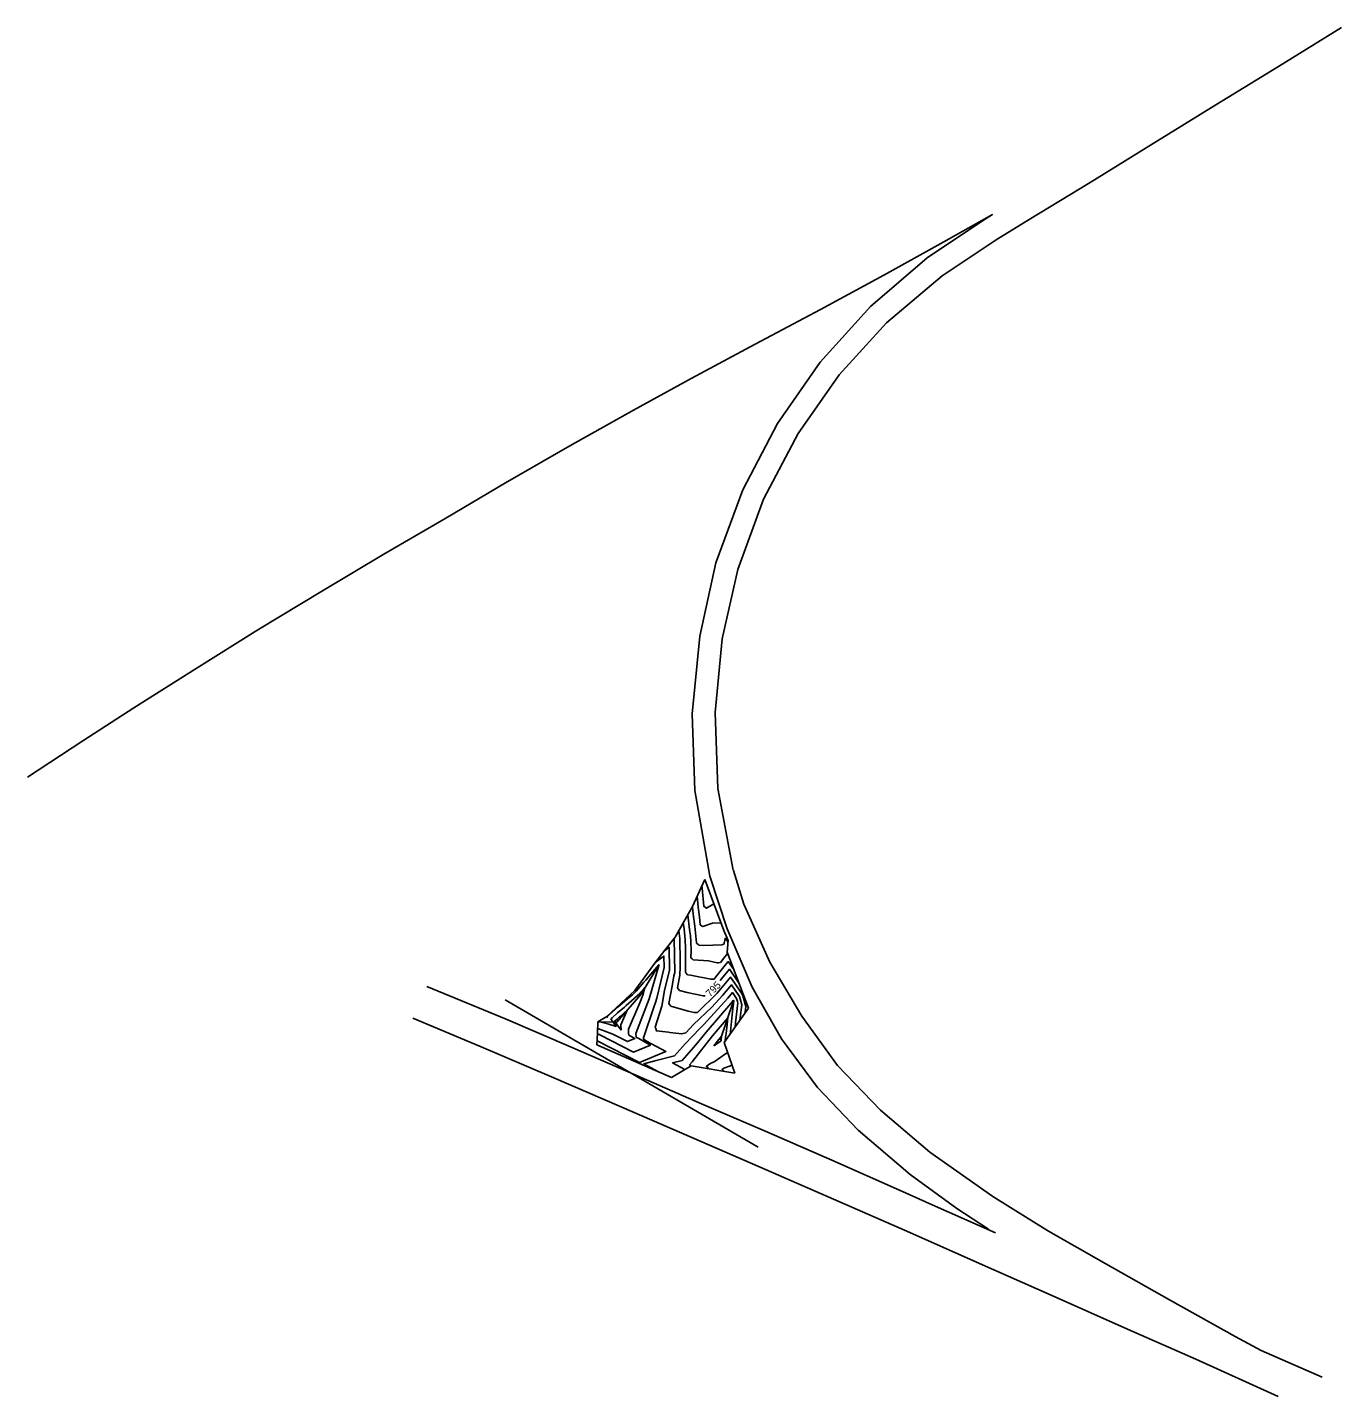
# Model space of a CAD drawing. Extents: x -5011 to 2414078, y -634 to 600034.
# Drawn here: x 2413180 to 2414078, y 599099 to 600034 of the extents above; entities that cross this region are included whole.
import ezdxf

# ---------------------------------------------------------------- set-up
doc = ezdxf.new("R2010")
doc.units = 0
for name, color, linetype in [('Default', 7, 'Continuous'), ('DESIGN - CONTOURS - Index with Text', 7, 'Continuous'), ('DESIGN - CONTOURS - Intermediate with optional Text', 7, 'Continuous'), ('DESIGN - DRAINAGE - Special Ditches', 7, 'Continuous'), ('DESIGN - ROW - Slope Lines', 7, 'Continuous'), ('SURVEY - TRANSPORTATION - Roads', 7, 'Continuous')]:
    doc.layers.add(name, color=color, linetype=linetype)

msp = doc.modelspace()

# ---------------------------------------------------------------- linework, layer by layer
at = {"layer": 'Default'}
msp.add_line((2413506.9, 599369.76), (2413679.75, 599269.14), dxfattribs=at)
at = {"layer": 'DESIGN - CONTOURS - Index with Text'}
for points in [[(2413641.24, 599447.27), (2413641.32, 599447.25), (2413641.38, 599446.55), (2413641.39, 599446.43), (2413641.39, 599446.43), (2413641.39, 599446.42), (2413641.39, 599446.42), (2413641.4, 599446.29), (2413641.4, 599446.28), (2413641.41, 599446.25), (2413641.44, 599445.95), (2413641.44, 599445.9), (2413642.57, 599433.63), (2413644.41, 599432.42), (2413644.41, 599432.42), (2413644.41, 599432.42), (2413644.42, 599432.42), (2413644.42, 599432.42), (2413644.42, 599432.42), (2413644.42, 599432.42), (2413649.52, 599435.25)], [(2413643.58, 599372.42), (2413642.68, 599372.4), (2413642.19, 599372.43), (2413631.18, 599374.64), (2413625.99, 599376.16), (2413625.13, 599377.27), (2413624.69, 599377.93), (2413626.32, 599386.57), (2413626.42, 599392.29), (2413626.37, 599395.71), (2413626.12, 599411.69), (2413625.49, 599417.09)], [(2413666.78, 599380.8), (2413660.04, 599390.56), (2413654.66, 599383.96), (2413653.83, 599382.95)], [(2413579.07, 599356.67), (2413579.96, 599357.44), (2413583.73, 599360.73), (2413588.34, 599364.74), (2413589.55, 599365.8), (2413598.98, 599374.01), (2413599.89, 599375.08), (2413600.09, 599375.31), (2413600.4, 599375.68), (2413600.72, 599376.04), (2413600.86, 599376.21), (2413602.39, 599378.02), (2413600.91, 599372.89), (2413598.94, 599367.7), (2413591.05, 599349.7), (2413591.21, 599346.72), (2413591.27, 599345.64), (2413591.57, 599345.44), (2413591.83, 599345.29), (2413595.51, 599343.27), (2413590.45, 599341.19), (2413580.48, 599346.29), (2413570.07, 599350.09)], [(2413570.54, 599354.85), (2413577.81, 599352.99), (2413582.7, 599351.57), (2413579.07, 599356.67)], [(2413633.62, 599324.5), (2413632.91, 599325.33), (2413634.72, 599327.34), (2413648.48, 599345.19), (2413658.96, 599357.41), (2413658.47, 599352.96), (2413657.77, 599346.62), (2413657.61, 599345.42), (2413657.48, 599344.4), (2413657.11, 599341.46)]]:
    msp.add_lwpolyline(points, dxfattribs=at)
at = {"layer": 'DESIGN - CONTOURS - Intermediate with optional Text'}
for points in [[(2413654.36, 599422.22), (2413648.5, 599422.08), (2413641.88, 599419.7), (2413640.96, 599420.19), (2413640.1, 599420.96), (2413639.55, 599426.45), (2413638.7, 599432.97), (2413638.25, 599437.92), (2413638.24, 599437.94), (2413638.23, 599438.05), (2413638.23, 599438.06), (2413638.23, 599438.07), (2413638.23, 599438.11), (2413638.23, 599438.11), (2413638.23, 599438.12), (2413638.23, 599438.12), (2413638.22, 599438.16), (2413638.03, 599440.22), (2413637.99, 599440.23)], [(2413659.34, 599400.13), (2413658.64, 599401.15), (2413658.08, 599400.46), (2413657.03, 599399.17), (2413653.92, 599395.25), (2413652.36, 599395.01), (2413651.69, 599395), (2413645.7, 599396.25), (2413635.38, 599396.97), (2413634.71, 599397.73), (2413633.82, 599398.48), (2413633.9, 599403.07), (2413633.8, 599409.48), (2413633.41, 599413.4), (2413633.04, 599416.24), (2413632.83, 599417.81), (2413631.67, 599427.85)], [(2413659.2, 599409.07), (2413657.1, 599411.73), (2413656.61, 599409.04), (2413656.61, 599409.04), (2413656.6, 599409.01), (2413656.41, 599407.99), (2413656.37, 599407.76), (2413654.8, 599407.22), (2413642.68, 599406.92), (2413639.26, 599407.16), (2413639.22, 599407.21), (2413637.93, 599408.29), (2413637.63, 599408.57), (2413636.48, 599419.93), (2413635.4, 599428.27), (2413634.8, 599432.91), (2413634.76, 599433.24)], [(2413663.06, 599390.47), (2413659.34, 599395.85), (2413656.37, 599392.21), (2413650.77, 599385.34), (2413649.57, 599383.84), (2413648.97, 599383.74), (2413647.39, 599383.72), (2413633.39, 599386.65), (2413631.5, 599386.78), (2413630.2, 599388.25), (2413629.99, 599388.42), (2413630.16, 599397.68), (2413630.04, 599405.36), (2413629.96, 599410.59), (2413629.08, 599418.16), (2413628.58, 599422.47)], [(2413670.69, 599360.51), (2413670.79, 599361.32), (2413671.2, 599365.05), (2413669.19, 599372.36), (2413668.87, 599373.51), (2413663.47, 599381.32), (2413660.74, 599385.27), (2413652.95, 599375.71), (2413651.82, 599374.34), (2413638.17, 599361.06), (2413637.45, 599361.05), (2413635.92, 599361.12), (2413631.89, 599361.93), (2413620, 599365.41), (2413619.83, 599365.63), (2413618.74, 599367.25), (2413620.96, 599379), (2413622.15, 599386), (2413622.71, 599388.3), (2413622.33, 599411.6), (2413621.85, 599411.24)], [(2413598.54, 599326.86), (2413616.66, 599334.31), (2413603.5, 599341.56), (2413602.55, 599342.08), (2413601.47, 599342.81), (2413601.42, 599343.66), (2413608.39, 599364.79), (2413609.55, 599367.85), (2413610.4, 599370.79), (2413615.5, 599391.76), (2413615.37, 599399.63), (2413613.79, 599398.44), (2413609.13, 599394.9)], [(2413667.29, 599355.75), (2413667.53, 599357.65), (2413668.5, 599366.34), (2413667.36, 599370.47), (2413666.92, 599372.05), (2413661.45, 599379.98), (2413655.43, 599372.61), (2413648.18, 599364.64), (2413635.52, 599352.74), (2413630.21, 599347.05), (2413629.36, 599346.88), (2413627.6, 599346.53), (2413619.45, 599347.45), (2413618.54, 599347.55), (2413610.22, 599348.48), (2413609.71, 599350.04), (2413609.38, 599351.01), (2413613.88, 599365.34), (2413615.69, 599376), (2413619.1, 599390.03), (2413618.85, 599405.62), (2413615.73, 599403.26), (2413615.49, 599403.07)], [(2413576.48, 599358.18), (2413577.94, 599359.45), (2413584.17, 599364.88), (2413591.76, 599371.5), (2413593.76, 599373.23), (2413596.38, 599375.52), (2413600.55, 599380.38), (2413601.48, 599381.47), (2413602.9, 599383.13), (2413604.35, 599384.81), (2413604.98, 599385.56), (2413611.76, 599393.55), (2413611.85, 599393.62), (2413611.89, 599393.64), (2413611.89, 599393.48), (2413611.79, 599393.06), (2413605.23, 599370.37), (2413596.25, 599346.72), (2413596.24, 599346.68), (2413596.37, 599344.23), (2413597.06, 599343.76), (2413597.66, 599343.43), (2413606.08, 599338.79), (2413594.49, 599334.02), (2413571.66, 599345.72), (2413569.88, 599346.37)], [(2413663.9, 599350.99), (2413664.28, 599353.97), (2413665.79, 599367.64), (2413665.53, 599368.59), (2413664.98, 599370.59), (2413662.15, 599374.69), (2413659.04, 599370.88), (2413642.59, 599352.81), (2413639.84, 599350.23), (2413629.88, 599339.54), (2413622.54, 599331.37), (2413610.01, 599328.14), (2413601.69, 599326), (2413611.53, 599320.56)], [(2413660.5, 599346.23), (2413660.51, 599346.26), (2413660.74, 599348.12), (2413661.02, 599350.29), (2413662.3, 599361.82), (2413663.09, 599368.94), (2413663.03, 599369.13), (2413662.85, 599369.4), (2413662.64, 599369.15), (2413660.97, 599367.3), (2413644.16, 599347.71), (2413638.39, 599340.22), (2413634.27, 599335.63), (2413627.73, 599328.35), (2413621.27, 599326.68), (2413629.59, 599322.08)], [(2413586.06, 599348.98), (2413585.87, 599352.72), (2413590.19, 599362.59), (2413585.34, 599358.36), (2413584.91, 599357.99), (2413583.3, 599356.59), (2413581.98, 599355.43), (2413581.66, 599355.16), (2413586.06, 599348.98)], [(2413575.88, 599358.06), (2413576.74, 599357.81), (2413576.48, 599358.18)], [(2413569.66, 599341.65), (2413598.54, 599326.86)], [(2413649.41, 599338.28), (2413652.8, 599342.68), (2413654.73, 599344.92), (2413654.64, 599344.11), (2413654.51, 599342.94), (2413654.48, 599342.72), (2413654.46, 599342.53), (2413654.36, 599341.77), (2413653.66, 599341.28), (2413652.74, 599340.63), (2413651.02, 599339.41), (2413650.82, 599339.27), (2413649.84, 599338.58), (2413649.67, 599338.46), (2413649.41, 599338.28)], [(2413646.12, 599322.67), (2413644.38, 599324.31), (2413647.38, 599326.41), (2413649.15, 599327.02), (2413649.69, 599327.4), (2413654.26, 599330.59), (2413656.69, 599332.29), (2413658.57, 599333.6), (2413659.02, 599333.29)], [(2413656.27, 599320.96), (2413655.05, 599322.11), (2413656.25, 599322.95), (2413660.23, 599324.34), (2413660.28, 599324.38), (2413660.74, 599324.7), (2413660.98, 599324.87), (2413661.17, 599325), (2413661.78, 599324.59), (2413662.1, 599324.58)]]:
    msp.add_lwpolyline(points, dxfattribs=at)
at = {"layer": 'DESIGN - DRAINAGE - Special Ditches'}
for points in [[(2413611.81, 599393.52), (2413599.7, 599373.59), (2413583.06, 599354.35), (2413570.29, 599354.7)], [(2413662.9, 599369.03), (2413653.78, 599342.11)]]:
    msp.add_lwpolyline(points, dxfattribs=at)
at = {"layer": 'DESIGN - ROW - Slope Lines'}
for p, q in [((2413643.35, 599451.87), (2413634.86, 599433.41)), ((2413656.3, 599417.01), (2413643.35, 599451.87)), ((2413622.92, 599412.61), (2413634.86, 599433.41)), ((2413634.86, 599433.41), (2413622.92, 599412.61)), ((2413659.33, 599410.32), (2413656.3, 599417.01)), ((2413616, 599403.72), (2413622.92, 599412.61)), ((2413622.92, 599412.61), (2413616, 599403.72)), ((2413658.48, 599402.37), (2413659.33, 599410.32)), ((2413658.48, 599402.37), (2413659.33, 599410.32)), ((2413609.08, 599394.83), (2413616, 599403.72)), ((2413616, 599403.72), (2413609.08, 599394.83)), ((2413665.85, 599383.22), (2413658.48, 599402.37)), ((2413665.85, 599383.22), (2413658.48, 599402.37)), ((2413595.38, 599376.1), (2413609.08, 599394.83)), ((2413609.08, 599394.83), (2413595.38, 599376.1)), ((2413673.23, 599364.08), (2413665.85, 599383.22)), ((2413673.23, 599364.08), (2413665.85, 599383.22)), ((2413576.28, 599358.3), (2413595.38, 599376.1)), ((2413595.38, 599376.1), (2413576.28, 599358.3)), ((2413656.46, 599340.55), (2413673.23, 599364.08)), ((2413656.46, 599340.55), (2413673.23, 599364.08)), ((2413570.29, 599354.7), (2413569.91, 599346.82)), ((2413570.29, 599354.7), (2413569.91, 599346.82)), ((2413576.28, 599358.3), (2413570.29, 599354.7)), ((2413576.28, 599358.3), (2413570.29, 599354.7)), ((2413569.91, 599346.82), (2413569.53, 599338.94)), ((2413569.91, 599346.82), (2413569.53, 599338.94)), ((2413569.53, 599338.94), (2413620.53, 599316.62)), ((2413569.53, 599338.94), (2413620.53, 599316.62)), ((2413663.83, 599319.69), (2413656.46, 599340.55)), ((2413663.83, 599319.69), (2413656.46, 599340.55)), ((2413620.53, 599316.62), (2413633.97, 599324.72)), ((2413620.53, 599316.62), (2413633.97, 599324.72)), ((2413633.97, 599324.72), (2413663.83, 599319.69)), ((2413633.97, 599324.72), (2413663.83, 599319.69))]:
    msp.add_line(p, q, dxfattribs=at)
for points in [[(2413634.86, 599433.41), (2413643.35, 599451.87)], [(2413643.35, 599451.87), (2413656.3, 599417.01), (2413659.33, 599410.32)]]:
    msp.add_lwpolyline(points, dxfattribs=at)
at = {"layer": 'SURVEY - TRANSPORTATION - Roads'}
for points in [[(2414078.34, 600034.13), (2414035.15, 600007.46), (2413992.42, 599981.31), (2413949.67, 599954.9), (2413906.44, 599928.26), (2413864.85, 599902.8), (2413842.4, 599889.05), (2413842.37, 599888.99), (2413805.36, 599864.42), (2413767.39, 599832.35), (2413735.16, 599796.79), (2413707.01, 599756.66), (2413683.47, 599711.76), (2413665.84, 599663.66), (2413655.19, 599616.44), (2413650.31, 599565.94), (2413652.22, 599514.07), (2413662.73, 599458.27)], [(2413180.45, 599521.94), (2413218.35, 599546.66), (2413253.29, 599569.11), (2413295.65, 599596.15), (2413337.9, 599622.41), (2413382.09, 599649.18), (2413424.05, 599674.18), (2413466.32, 599698.85), (2413507.1, 599722.86), (2413551.14, 599748.29), (2413594.51, 599772.62), (2413633.95, 599794.16), (2413677.72, 599817.65), (2413722.31, 599841.29), (2413765.53, 599864.79), (2413806.66, 599887.56), (2413839.79, 599906.26), (2413834.41, 599902.9), (2413834.36, 599902.82), (2413795.28, 599876.74), (2413756.4, 599843.51), (2413722.15, 599805.49), (2413692.84, 599763.54), (2413669.15, 599718.21), (2413650.91, 599668.36), (2413639.79, 599618.16), (2413634.7, 599565.18), (2413636.54, 599512.71), (2413646.76, 599454.19)], [(2413646.76, 599454.19), (2413658.45, 599418.29), (2413675.68, 599378.45), (2413695.59, 599343.14), (2413720.37, 599309.71), (2413747.95, 599280.66), (2413783.49, 599250.4), (2413815.39, 599227.06), (2413837.01, 599213.06)], [(2414064.97, 599111.98), (2414023.33, 599130.2), (2414005.61, 599139.66), (2413960.7, 599164.74), (2413917.34, 599189.33), (2413878.08, 599211.65), (2413840.16, 599235.36), (2413797, 599265.56), (2413763.37, 599294.35), (2413734.02, 599324.8), (2413709.46, 599358.6), (2413687.7, 599395.51), (2413669.84, 599434.96), (2413662.82, 599457.99)], [(2413841.85, 599210.45), (2413800.75, 599228.75), (2413776.24, 599239.71), (2413730.08, 599260.13), (2413685.57, 599279.5), (2413641.1, 599298.73), (2413596.2, 599318.21), (2413552.99, 599336.8), (2413507.63, 599356.41), (2413453.32, 599378.76)], [(2413841.85, 599210.45), (2413800.75, 599228.75), (2413776.24, 599239.71), (2413730.08, 599260.13), (2413685.57, 599279.5), (2413641.1, 599298.73), (2413596.2, 599318.21), (2413552.99, 599336.8), (2413507.63, 599356.41), (2413453.32, 599378.76)], [(2413443.8, 599357.24), (2413490.48, 599337.52), (2413538.61, 599317.14), (2413586.5, 599296.46), (2413634.39, 599275.75), (2413681.2, 599255.42), (2413731.11, 599233.48), (2413783.29, 599210.68), (2413830.88, 599189.58), (2413879.79, 599167.81), (2413932.06, 599144.68), (2413978.65, 599124.08), (2414035.07, 599098.6)], [(2413443.8, 599357.24), (2413490.48, 599337.52), (2413538.61, 599317.14), (2413586.5, 599296.46), (2413634.39, 599275.75), (2413681.2, 599255.42), (2413731.11, 599233.48), (2413783.29, 599210.68), (2413830.88, 599189.58), (2413879.79, 599167.81), (2413932.06, 599144.68), (2413978.65, 599124.08), (2414035.07, 599098.6)]]:
    msp.add_lwpolyline(points, dxfattribs=at)

# ---------------------------------------------------------------- texts
at = {"layer": 'DESIGN - CONTOURS - Index with Text'}
msp.add_text('795', height=5, rotation=45.75062, dxfattribs=at).set_placement((2413646.92, 599371.32))

doc.saveas('drawing.dxf')
